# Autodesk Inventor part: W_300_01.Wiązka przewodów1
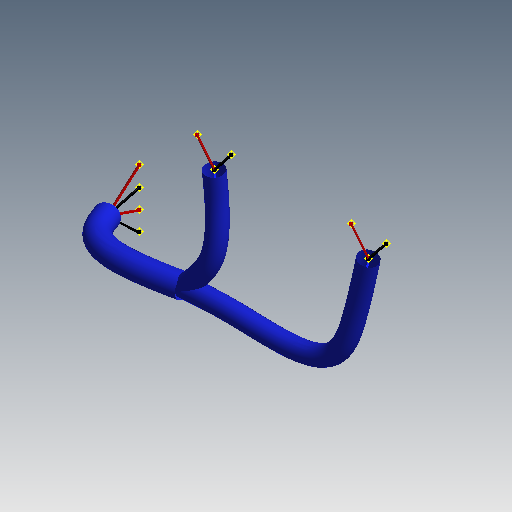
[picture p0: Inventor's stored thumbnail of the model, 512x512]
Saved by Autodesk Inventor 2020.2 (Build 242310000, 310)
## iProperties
Created: 2014-09
Part Number: W_300_01.Wiązka przewodów1
Material: Ogólne
Document SubType Name: Modelowanie
Designer: F.Stasiak
Appearance: Ogólne
Catalog Web Link: www.expertbooks.pl
Manager: www.cadconsulting.pl
Company: Fabian Stasiak CAD Consulting
Key:2|1|1|0|4|0|0|0|4|0|0|0|Level:2: <CableProperty entityType="Connector" version="1.0"><ID editable="" value=""/><UserDefined/><Name editable="True" value=""/><Refdes editable="True" value="KOND_
Key:2|1|1|0|4|0|0|0|5|0|0|0|Level:2: <CableProperty entityType="Connector" version="1.0"><ID editable="" value=""/><UserDefined/><Name editable="True" value=""/><Refdes editable="True" value="KOND_
Key:2|1|1|0|4|0|0|0|8|0|0|0|Level:2: <CableProperty entityType="Connector" version="1.0"><ID editable="" value=""/><UserDefined/><Name editable="True" value=""/><Refdes editable="True" value="LISTW
GlobalPropertyList: <PropertyList/>
Author: F.Stasiak
Subject: Zbiór ćwiczeń. Autodesk Inventor 2020. Kurs Professional
## Parameters: d66 = 0, d67 = 0, d68 = 0, d69 = 0, d70 = 0, d71 = 0, d72 = 0, d73 = 0, d74 = 0, d75 = 0, d76 = 0, d77 = 0, d78 = 0, d79 = 0, d80 = 0, d81 = 0, d82 = 0, d83 = 0, d84 = 0, d85 = 0, d86 = 0, d87 = 0
